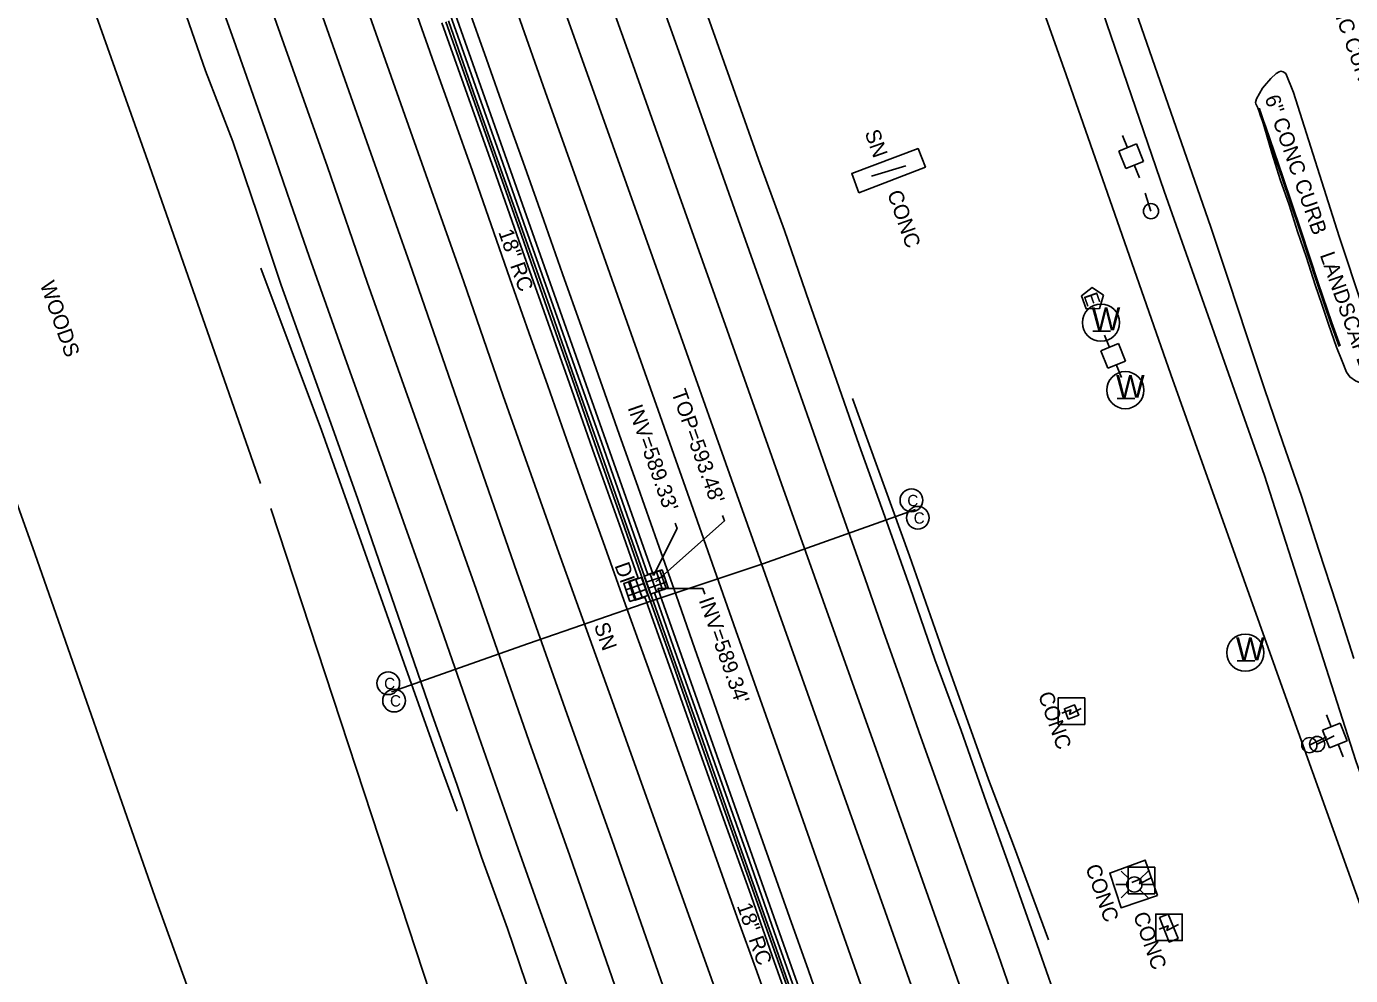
# Model space of a CAD drawing. Extents: x 2004847 to 2009016, y 1134161 to 1140101.
# Drawn here: x 2005569.8 to 2005919.4, y 1137558.5 to 1137809.1 of the extents above; entities that cross this region are included whole.
import ezdxf

# ---------------------------------------------------------------- set-up
doc = ezdxf.new("R2010")
doc.units = 0
for name, color, linetype in [('RD_DTM_BkLn1', 7, 'Continuous'), ('RD_EX_BldgApp', 7, 'Continuous'), ('RD_EX_Conc', 7, 'Continuous'), ('RD_EX_Curb', 7, 'Continuous'), ('RD_EX_DR_Inlet', 7, 'Continuous'), ('RD_EX_DR_Inlet_txCode', 7, 'Continuous'), ('RD_EX_DR_Pipe', 7, 'Continuous'), ('RD_EX_DR_Pipe_txCode', 7, 'Continuous'), ('RD_EX_Fence_Other', 7, 'Continuous'), ('RD_EX_GuardRail', 7, 'Continuous'), ('RD_EX_H2O', 7, 'Continuous'), ('RD_EX_Pavement_Markings', 7, 'Continuous'), ('RD_EX_Road', 7, 'Continuous'), ('RD_EX_SU_Elec', 7, 'Continuous'), ('RD_EX_UT', 7, 'Continuous'), ('RD_EX_VEG', 7, 'Continuous'), ('RD_Sketch3', 7, 'Continuous')]:
    doc.layers.add(name, color=color, linetype=linetype)

msp = doc.modelspace()

# ---------------------------------------------------------------- linework, layer by layer
at = {"layer": 'RD_DTM_BkLn1'}
msp.add_lwpolyline([(2005896.58, 1137782.63), (2005898.54, 1137775.67), (2005900.8, 1137768.7), (2005903.13, 1137762), (2005905.37, 1137754.95), (2005907.71, 1137748.06), (2005910.03, 1137740.87), (2005911.81, 1137735.74), (2005913.56, 1137730.47), (2005915.63, 1137724.38), (2005917.14, 1137720.71), (2005918.26, 1137717.78), (2005919.17, 1137716.55), (2005920.67, 1137715.47), (2005923.24, 1137714.42), (2005928.77, 1137713.55), (2005929.35, 1137713.96), (2005928.39, 1137717.21)], dxfattribs=at)
at = {"layer": 'RD_EX_BldgApp'}
msp.add_line((2005801.91, 1137772.28), (2005792.88, 1137769.57), dxfattribs=at)
msp.add_lwpolyline([(2005666.13, 1137633.4), (2005702.31, 1137646.16), (2005734.91, 1137657.41), (2005764.21, 1137667.23), (2005804.53, 1137681.53)], dxfattribs=at)
msp.add_lwpolyline([(2005666.13, 1137633.4), (2005702.31, 1137646.16), (2005734.91, 1137657.41), (2005764.21, 1137667.23), (2005804.53, 1137681.53)], dxfattribs=at)
for centre in [(2005803.43, 1137683.96), (2005803.43, 1137683.96), (2005805.12, 1137679.35), (2005805.12, 1137679.35), (2005665.3, 1137635.66), (2005666.85, 1137631.07)]:
    msp.add_circle(centre, 3, dxfattribs=at)
at = {"layer": 'RD_EX_Conc'}
for points in [[(2005680.52, 1137810.28), (2005687.18, 1137791.43), (2005693.85, 1137772.58), (2005700.54, 1137753.73), (2005707.21, 1137734.88), (2005713.85, 1137716.01), (2005720.48, 1137697.14), (2005727.14, 1137678.29), (2005733.79, 1137659.43), (2005740.49, 1137640.59), (2005747.16, 1137621.74), (2005753.85, 1137602.89), (2005760.49, 1137584.03), (2005767.18, 1137565.18), (2005773.87, 1137546.33), (2005780.5, 1137527.47), (2005787.18, 1137508.62), (2005793.87, 1137489.77), (2005800.53, 1137470.92), (2005807.19, 1137452.06), (2005813.89, 1137433.22), (2005820.56, 1137414.37)], [(2005681.18, 1137810.52), (2005687.84, 1137791.67), (2005694.51, 1137772.82), (2005701.21, 1137753.96), (2005707.88, 1137735.11), (2005714.51, 1137716.25), (2005721.16, 1137697.38), (2005727.78, 1137678.52), (2005734.42, 1137659.66), (2005741.13, 1137640.82), (2005747.79, 1137621.96), (2005754.44, 1137603.1), (2005761.08, 1137584.24), (2005767.77, 1137565.39), (2005774.43, 1137546.53), (2005781.07, 1137527.67), (2005787.74, 1137508.82), (2005794.43, 1137489.97), (2005801.1, 1137471.13), (2005807.76, 1137452.26), (2005814.47, 1137433.43), (2005821.16, 1137414.58)], [(2005789.56, 1137765.12), (2005807.13, 1137771.95), (2005805.2, 1137776.83), (2005787.67, 1137770.23), (2005789.56, 1137765.12)], [(2005844.79, 1137626.21), (2005843.8, 1137628.92), (2005846.52, 1137629.96), (2005847.62, 1137627.27), (2005844.79, 1137626.21)], [(2005868.4, 1137579.62), (2005865.1, 1137588.99), (2005855.79, 1137585.56), (2005858.8, 1137576.4), (2005868.4, 1137579.62)], [(2005868.9, 1137573.79), (2005871.52, 1137567.33), (2005873.82, 1137568.3), (2005871.17, 1137574.66), (2005868.9, 1137573.79)]]:
    msp.add_lwpolyline(points, dxfattribs=at)
at = {"layer": 'RD_EX_Curb'}
msp.add_lwpolyline([(2005895.33, 1137787.5), (2005895.52, 1137786.82), (2005895.84, 1137785.74), (2005896.4, 1137784.14), (2005896.88, 1137782.7), (2005901.61, 1137769.1), (2005906.22, 1137755.24), (2005910.85, 1137741.35), (2005914.44, 1137730.78), (2005916.59, 1137724.71)], dxfattribs=at)
at = {"layer": 'RD_EX_DR_Inlet'}
for p, q in [((2005736.1, 1137665.05), (2005737.72, 1137660.32)), ((2005728.03, 1137660.36), (2005732.76, 1137661.98)), ((2005729.09, 1137662.52), (2005730.71, 1137657.79)), ((2005730.7, 1137663.07), (2005732.32, 1137658.34)), ((2005733.43, 1137662.33), (2005738.16, 1137663.96)), ((2005733.98, 1137660.73), (2005738.71, 1137662.35)), ((2005734.49, 1137664.49), (2005736.11, 1137659.76)), ((2005728.59, 1137658.75), (2005733.32, 1137660.37))]:
    msp.add_line(p, q, dxfattribs=at)
for points in [[(2005734.5, 1137659.21), (2005732.88, 1137663.94), (2005737.61, 1137665.56), (2005739.23, 1137660.84)], [(2005729.11, 1137657.24), (2005727.48, 1137661.97), (2005732.21, 1137663.59), (2005733.83, 1137658.86)]]:
    msp.add_lwpolyline(points, close=True, dxfattribs=at)
at = {"layer": 'RD_EX_DR_Inlet_txCode'}
for points in [[(2005735.92, 1137662.41), (2005754.04, 1137678.56), (2005753.56, 1137679.93)], [(2005735.37, 1137664.11), (2005741.54, 1137676.56), (2005741.05, 1137677.95)], [(2005736.5, 1137660.69), (2005748.37, 1137660.67), (2005748.91, 1137659.15)]]:
    msp.add_lwpolyline(points, dxfattribs=at)
at = {"layer": 'RD_EX_DR_Pipe'}
for p, q in [((2005671.02, 1137846.21), (2005735.37, 1137664.11)), ((2005736.5, 1137660.69), (2005798.12, 1137486.36))]:
    msp.add_line(p, q, dxfattribs=at)
at = {"layer": 'RD_EX_Fence_Other'}
for points in [[(2005949.11, 1137501.97), (2005933.7, 1137544.22), (2005901.74, 1137633.37), (2005871.92, 1137717.16), (2005844.24, 1137796.25), (2005814.93, 1137879.26), (2005785.94, 1137962.71), (2005762.81, 1138027.41)], [(2005544.1, 1137747.93), (2005571.98, 1137669.9), (2005603.8, 1137579.06), (2005637.48, 1137485.82), (2005667.17, 1137401.41)]]:
    msp.add_lwpolyline(points, dxfattribs=at)
at = {"layer": 'RD_EX_GuardRail'}
for points in [[(2005631.66, 1137745.23), (2005647.66, 1137702.51), (2005658.16, 1137673), (2005668.53, 1137643.58), (2005678.98, 1137614.08), (2005683.52, 1137601.87)], [(2005839.64, 1137567.95), (2005830.4, 1137592.92), (2005823.79, 1137610.28), (2005813.42, 1137639.38), (2005802.89, 1137669.28), (2005787.91, 1137710.85)]]:
    msp.add_lwpolyline(points, dxfattribs=at)
at = {"layer": 'RD_EX_H2O'}
msp.add_lwpolyline([(2005471.87, 1138887.95), (2005497.78, 1138815.38), (2005524.51, 1138742.04), (2005550.26, 1138669.15), (2005576.78, 1138597.72), (2005601.39, 1138524.1), (2005626.92, 1138450.25), (2005654.19, 1138374.96), (2005680.69, 1138302.53), (2005706.44, 1138229.22), (2005734.3, 1138151.24), (2005761.38, 1138075.97), (2005788.89, 1137997.69), (2005816.8, 1137918.93), (2005844.2, 1137841.48), (2005870.19, 1137765.6), (2005896.66, 1137690.53), (2005920.78, 1137615.18), (2005947.05, 1137540.88)], dxfattribs=at)
at = {"layer": 'RD_EX_Pavement_Markings'}
for points in [[(2005650.65, 1138023.79), (2005661.36, 1137993.16), (2005675.57, 1137952.57), (2005689.8, 1137912.08), (2005700.62, 1137881.25), (2005715.02, 1137840.66), (2005729.45, 1137800.21), (2005740.39, 1137769.42), (2005754.76, 1137728.86), (2005769.14, 1137688.32), (2005780.1, 1137657.44), (2005794.53, 1137616.94), (2005808.89, 1137576.39), (2005823.14, 1137536.02), (2005833.8, 1137505.87), (2005848.16, 1137465.29), (2005862.54, 1137424.75)], [(2005638.93, 1138020.85), (2005649.77, 1137989.86), (2005663.98, 1137949.28), (2005678.2, 1137908.74), (2005692.41, 1137868.56), (2005702.98, 1137838.35), (2005717.35, 1137797.86), (2005731.8, 1137757.37), (2005742.51, 1137727.22), (2005756.88, 1137686.7), (2005771.33, 1137646.14), (2005782.09, 1137615.98), (2005796.49, 1137575.39), (2005810.82, 1137534.74), (2005825.09, 1137494.13), (2005835.74, 1137463.95), (2005849.99, 1137423.41)], [(2005628.29, 1138015.02), (2005639.01, 1137984.69), (2005653.3, 1137944.12), (2005667.51, 1137903.59), (2005678.25, 1137873.06), (2005692.46, 1137832.47), (2005706.73, 1137791.91), (2005717.65, 1137761.23), (2005732.03, 1137720.7), (2005746.31, 1137680.15), (2005757.06, 1137649.63), (2005771.38, 1137609.11), (2005785.67, 1137568.57), (2005799.94, 1137528.08), (2005810.82, 1137497.03), (2005825.14, 1137456.53), (2005839.37, 1137416.27)], [(2005570.31, 1137995.12), (2005581.13, 1137964.85), (2005595.41, 1137924.24), (2005609.59, 1137883.9), (2005620.42, 1137853.23), (2005634.8, 1137812.65), (2005649.23, 1137771.98), (2005659.76, 1137741.51), (2005674.17, 1137700.87), (2005688.48, 1137660.47), (2005702.51, 1137620.29), (2005713.22, 1137590.13), (2005727.31, 1137549.48), (2005741.41, 1137508.86), (2005752.24, 1137478.53), (2005766.92, 1137438.17), (2005781.39, 1137397.9)], [(2005602.85, 1137974.8), (2005617.38, 1137933.98), (2005631.61, 1137893.38), (2005642.64, 1137862.53), (2005656.88, 1137821.85), (2005671.18, 1137781.44), (2005685.25, 1137741.64), (2005695.66, 1137711.54), (2005709.89, 1137671.3), (2005724.46, 1137631.01), (2005735.24, 1137600.65), (2005749.69, 1137560.37), (2005764.04, 1137519.84), (2005778.16, 1137479.48), (2005788.73, 1137449.51), (2005803, 1137409.01)], [(2005591.82, 1137970.6), (2005606.28, 1137929.97), (2005620.66, 1137889.23), (2005631.47, 1137858.16), (2005645.93, 1137817.63), (2005660.14, 1137777.13), (2005670.99, 1137746.52), (2005685.12, 1137705.8), (2005699.26, 1137665.03), (2005713.5, 1137624.72), (2005724.31, 1137594.45), (2005738.53, 1137553.85), (2005752.77, 1137513.17), (2005763.43, 1137483.09), (2005778, 1137442.79), (2005792.39, 1137402.39)], [(2005619.48, 1137819.55), (2005624.51, 1137805.41), (2005629.62, 1137790.89), (2005634.63, 1137776.57), (2005639.53, 1137762.5), (2005644.44, 1137748.37), (2005649.45, 1137734.19), (2005654.39, 1137720.26), (2005659.39, 1137706.28), (2005664.33, 1137692.41), (2005669.35, 1137678.31), (2005674.38, 1137664.16), (2005679.39, 1137649.93), (2005684.33, 1137635.76), (2005689.24, 1137621.61), (2005694.14, 1137607.48), (2005699.09, 1137593.4), (2005704.1, 1137579.29), (2005709.04, 1137565.47), (2005714.01, 1137551.5)], [(2005736.91, 1137816.78), (2005741.98, 1137802.45), (2005746.94, 1137788.47), (2005751.7, 1137775.02), (2005756.71, 1137760.84), (2005761.56, 1137747.18), (2005766.38, 1137733.52), (2005771.4, 1137719.35), (2005776.42, 1137705.16), (2005781.28, 1137691.32), (2005786.3, 1137677.13), (2005791.21, 1137663.22), (2005796.09, 1137649.28), (2005801.06, 1137635.21), (2005805.92, 1137621.44), (2005810.98, 1137607.16), (2005816.1, 1137592.77), (2005821.21, 1137578.3), (2005826.29, 1137564.04), (2005831.11, 1137550.32)], [(2005672.54, 1137813.22), (2005677.45, 1137799.18), (2005682.52, 1137784.95), (2005687.57, 1137770.85), (2005692.51, 1137756.65), (2005697.43, 1137742.54), (2005702.44, 1137728.24), (2005707.44, 1137714.15), (2005712.37, 1137700.1), (2005717.39, 1137685.94), (2005722.49, 1137671.77), (2005727.48, 1137657.57), (2005732.51, 1137643.7), (2005737.56, 1137629.78), (2005742.57, 1137615.7), (2005747.6, 1137601.59), (2005752.52, 1137587.75), (2005757.46, 1137573.81), (2005762.62, 1137559.58), (2005767.67, 1137545.48)], [(2005686.26, 1137814.53), (2005691.26, 1137800.4), (2005696.29, 1137786.21), (2005701.34, 1137772.01), (2005706.34, 1137757.86), (2005711.32, 1137743.78), (2005716.3, 1137729.63), (2005721.32, 1137715.45), (2005726.28, 1137701.43), (2005731.3, 1137687.3), (2005736.29, 1137673.09), (2005741.31, 1137658.88), (2005746.27, 1137644.73), (2005751.25, 1137630.54), (2005756.22, 1137616.41), (2005761.25, 1137602.21), (2005766.26, 1137588.05), (2005771.24, 1137573.92), (2005776.23, 1137559.83), (2005781.22, 1137545.69)]]:
    msp.add_lwpolyline(points, dxfattribs=at)
at = {"layer": 'RD_EX_Road'}
for points in [[(2005610.52, 1137816.19), (2005617.08, 1137797.34), (2005624.29, 1137778.69), (2005630.74, 1137759.78), (2005637.03, 1137740.75), (2005643.84, 1137721.93), (2005650.6, 1137703.09), (2005657.24, 1137684.23), (2005663.8, 1137665.35), (2005670.26, 1137646.48), (2005676.83, 1137627.61), (2005683.5, 1137608.76), (2005689.91, 1137589.74), (2005696.78, 1137570.94), (2005703.25, 1137552.03), (2005709.92, 1137533.21), (2005716.27, 1137514.25), (2005722.92, 1137495.46), (2005729.7, 1137476.61), (2005736.39, 1137457.72), (2005743.18, 1137438.88), (2005749.96, 1137420.02)], [(2005681.67, 1137812.2), (2005688.35, 1137793.34), (2005694.99, 1137774.47), (2005701.65, 1137755.62), (2005708.31, 1137736.78), (2005714.97, 1137717.91), (2005721.65, 1137699.06), (2005728.3, 1137680.22), (2005733.88, 1137664.34), (2005735.97, 1137665.07), (2005736.41, 1137665.23), (2005736.98, 1137665.43), (2005738.71, 1137660.65), (2005738.14, 1137660.44), (2005737.54, 1137660.23), (2005735.6, 1137659.54), (2005740.53, 1137645.49), (2005747.21, 1137626.63), (2005753.9, 1137607.78), (2005760.57, 1137588.92), (2005767.21, 1137570.06), (2005773.86, 1137551.21)], [(2005749.68, 1137811.68), (2005756.36, 1137792.83), (2005763.03, 1137773.97), (2005769.93, 1137755.22), (2005776.41, 1137736.28), (2005783.05, 1137717.42), (2005789.65, 1137698.51), (2005796.44, 1137679.72), (2005803.09, 1137660.84), (2005809.62, 1137641.96), (2005816.53, 1137623.21), (2005823.16, 1137604.35), (2005829.9, 1137585.5), (2005836.6, 1137566.64), (2005843.24, 1137547.8), (2005850.12, 1137529), (2005856.67, 1137510.13), (2005863.23, 1137491.24), (2005869.96, 1137472.36), (2005876.59, 1137453.53), (2005883.19, 1137434.67), (2005889.89, 1137415.79)], [(2005862.76, 1137812.73), (2005867.67, 1137798.56), (2005872.6, 1137784.42), (2005877.54, 1137770.25), (2005882.45, 1137756.08), (2005887.21, 1137741.86), (2005891.9, 1137727.62), (2005896.69, 1137713.41), (2005901.48, 1137699.21), (2005906.4, 1137685.04), (2005911.02, 1137670.77), (2005915.65, 1137656.5), (2005920.23, 1137642.2)], [(2005679.46, 1137810.04), (2005686.11, 1137791.22), (2005693.18, 1137771.4), (2005699.78, 1137752.53), (2005706.46, 1137733.69), (2005713.13, 1137714.84), (2005719.73, 1137695.98), (2005726.76, 1137676.22), (2005731.25, 1137663.37), (2005728.75, 1137662.48), (2005730.15, 1137658.51), (2005730.48, 1137657.56), (2005733.06, 1137658.42), (2005733.42, 1137657.38), (2005740.46, 1137637.59), (2005747.15, 1137618.72), (2005753.84, 1137599.87), (2005760.56, 1137581.03), (2005767.21, 1137562.21), (2005773.84, 1137543.32)], [(2005904.3, 1137791.67), (2005902.31, 1137796.62), (2005901.61, 1137797.05), (2005901, 1137797.27), (2005900.53, 1137797.11), (2005899.77, 1137796.64), (2005898.29, 1137795.35), (2005896.67, 1137793.43), (2005896.12, 1137792.77), (2005895.32, 1137791.39), (2005894.53, 1137790), (2005894.27, 1137789.03), (2005894.32, 1137788.61), (2005894.88, 1137787.55), (2005895.23, 1137786.59), (2005895.58, 1137785.48), (2005896.09, 1137784.06), (2005896.58, 1137782.63), (2005901.35, 1137769.01), (2005905.99, 1137755.15), (2005910.59, 1137741.25), (2005914.17, 1137730.64), (2005916.35, 1137724.6)], [(2005928.39, 1137717.21), (2005922.49, 1137735.03), (2005916.32, 1137753.61), (2005904.3, 1137791.67)]]:
    msp.add_lwpolyline(points, dxfattribs=at)
at = {"layer": 'RD_EX_SU_Elec'}
msp.add_lwpolyline([(2005854.12, 1137738.08), (2005851.17, 1137740.11), (2005848.32, 1137737.93), (2005849.52, 1137734.55), (2005853.1, 1137734.64)], close=True, dxfattribs=at)
at = {"layer": 'RD_EX_UT'}
for p, q in [((2005859.16, 1137780.27), (2005860.45, 1137777.05)), ((2005862.82, 1137778.04), (2005858.17, 1137776.18)), ((2005864.67, 1137773.39), (2005862.82, 1137778.04)), ((2005858.17, 1137776.18), (2005860.03, 1137771.54)), ((2005860.03, 1137771.54), (2005864.67, 1137773.39)), ((2005862.26, 1137772.51), (2005863.61, 1137769.13)), ((2005866.68, 1137760.29), (2005865.14, 1137765.05)), ((2005851.35, 1137728.66), (2005855.98, 1137728.66)), ((2005858.06, 1137725.32), (2005853.42, 1137723.46)), ((2005854.41, 1137727.55), (2005855.7, 1137724.33)), ((2005859.92, 1137720.67), (2005858.06, 1137725.32)), ((2005853.42, 1137723.46), (2005855.27, 1137718.82)), ((2005855.27, 1137718.82), (2005859.92, 1137720.67)), ((2005857.51, 1137719.79), (2005858.86, 1137716.41)), ((2005857.79, 1137710.84), (2005862.42, 1137710.84)), ((2005889.46, 1137641.54), (2005894.09, 1137641.54)), ((2005912.98, 1137627.36), (2005914.27, 1137624.14)), ((2005916.63, 1137625.13), (2005911.99, 1137623.27)), ((2005911.99, 1137623.27), (2005913.84, 1137618.63)), ((2005918.49, 1137620.48), (2005916.63, 1137625.13)), ((2005908.49, 1137619.33), (2005912.99, 1137621.51)), ((2005910.54, 1137619.6), (2005915.04, 1137621.77)), ((2005913.84, 1137618.63), (2005918.49, 1137620.48)), ((2005916.08, 1137619.6), (2005917.43, 1137616.22)), ((2005858.83, 1137586.08), (2005860.92, 1137583.99)), ((2005863.73, 1137583.92), (2005865.9, 1137586.08)), ((2005860.29, 1137582.55), (2005857.36, 1137582.55)), ((2005858.83, 1137579.01), (2005860.9, 1137581.09)), ((2005863.75, 1137581.16), (2005865.9, 1137579.01)), ((2005867.36, 1137582.55), (2005864.29, 1137582.55))]:
    msp.add_line(p, q, dxfattribs=at)
for points in [[(2005842.2, 1137624.79), (2005842.2, 1137631.79), (2005849.2, 1137631.79), (2005849.2, 1137624.79)], [(2005860.68, 1137580.09), (2005860.68, 1137587.09), (2005867.68, 1137587.09), (2005867.68, 1137580.09)], [(2005867.92, 1137567.71), (2005867.92, 1137574.71), (2005874.92, 1137574.71), (2005874.92, 1137567.71)]]:
    msp.add_lwpolyline(points, close=True, dxfattribs=at)
for points in [[(2005843.1, 1137627.78), (2005845.52, 1137628.68), (2005845.18, 1137627.43), (2005848.22, 1137629.03)], [(2005861.58, 1137583.08), (2005864, 1137583.98), (2005863.65, 1137582.74), (2005866.7, 1137584.33)], [(2005868.81, 1137570.71), (2005871.24, 1137571.61), (2005870.89, 1137570.36), (2005873.94, 1137571.95)]]:
    msp.add_lwpolyline(points, dxfattribs=at)
for centre, radius in [((2005866.68, 1137760.29), 2), ((2005853.48, 1137730.87), 4.91), ((2005859.92, 1137713.04), 4.91), ((2005891.59, 1137643.74), 4.91), ((2005908.49, 1137619.33), 2), ((2005910.54, 1137619.6), 2), ((2005862.29, 1137582.53), 2)]:
    msp.add_circle(centre, radius, dxfattribs=at)
at = {"layer": 'RD_EX_VEG'}
for points in [[(2005631.57, 1137688.41), (2005602.31, 1137772.31), (2005569.94, 1137863.34), (2005535.14, 1137958.28), (2005501.77, 1138049.88), (2005469.93, 1138142.96)], [(2005718.89, 1137413.27), (2005693.64, 1137501.22), (2005662.96, 1137594.49), (2005634.34, 1137681.77)]]:
    msp.add_lwpolyline(points, dxfattribs=at)

# ---------------------------------------------------------------- texts
at = {"layer": 'RD_EX_BldgApp'}
for p in [(2005802.35, 1137682.4), (2005802.35, 1137682.4), (2005804.03, 1137677.79), (2005804.03, 1137677.79), (2005664.22, 1137634.1), (2005665.77, 1137629.51)]:
    msp.add_text('C', height=3, dxfattribs=at).set_placement(p)
at = {"layer": 'RD_EX_DR_Inlet_txCode'}
for s, p in [("TOP=593.48'", (2005740, 1137712.46)), ("INV=589.33'", (2005728.45, 1137708.41)), ('DI', (2005725.01, 1137666.78)), ("INV=589.34'", (2005747.24, 1137657.6))]:
    msp.add_text(s, height=4, rotation=289.4494, dxfattribs=at).set_placement(p)
at = {"layer": 'RD_EX_DR_Pipe_txCode'}
for p in [(2005694.31, 1137754.79), (2005757.29, 1137576.91)]:
    msp.add_text('18" RC', height=4, rotation=289.4494, dxfattribs=at).set_placement(p)
at = {"layer": 'RD_EX_SU_Elec'}
msp.add_text('E', height=3.75, rotation=289.4494, dxfattribs=at).set_placement((2005848.79, 1137738.05))
at = {"layer": 'RD_EX_UT'}
for p in [(2005851.02, 1137728.87), (2005857.45, 1137711.04), (2005889.12, 1137641.74)]:
    msp.add_text('W', height=6, dxfattribs=at).set_placement(p)
at = {"layer": 'RD_Sketch3'}
for s, p in [('6" CONC CURB', (2005909.75, 1137827.58)), ('6" CONC CURB', (2005896.63, 1137790.2)), ('SN', (2005791.04, 1137781.05)), ('CONC', (2005796.97, 1137765.04)), ('LANDSCAPE', (2005911.2, 1137748.74)), ('WOODS', (2005573.29, 1137741.02)), ('SN', (2005719.55, 1137650.92)), ('CONC', (2005836.8, 1137632.64)), ('CONC', (2005849.3, 1137587.07)), ('CONC', (2005861.92, 1137574.49))]:
    msp.add_text(s, height=4, rotation=289.4494, dxfattribs=at).set_placement(p)

doc.saveas('drawing.dxf')
